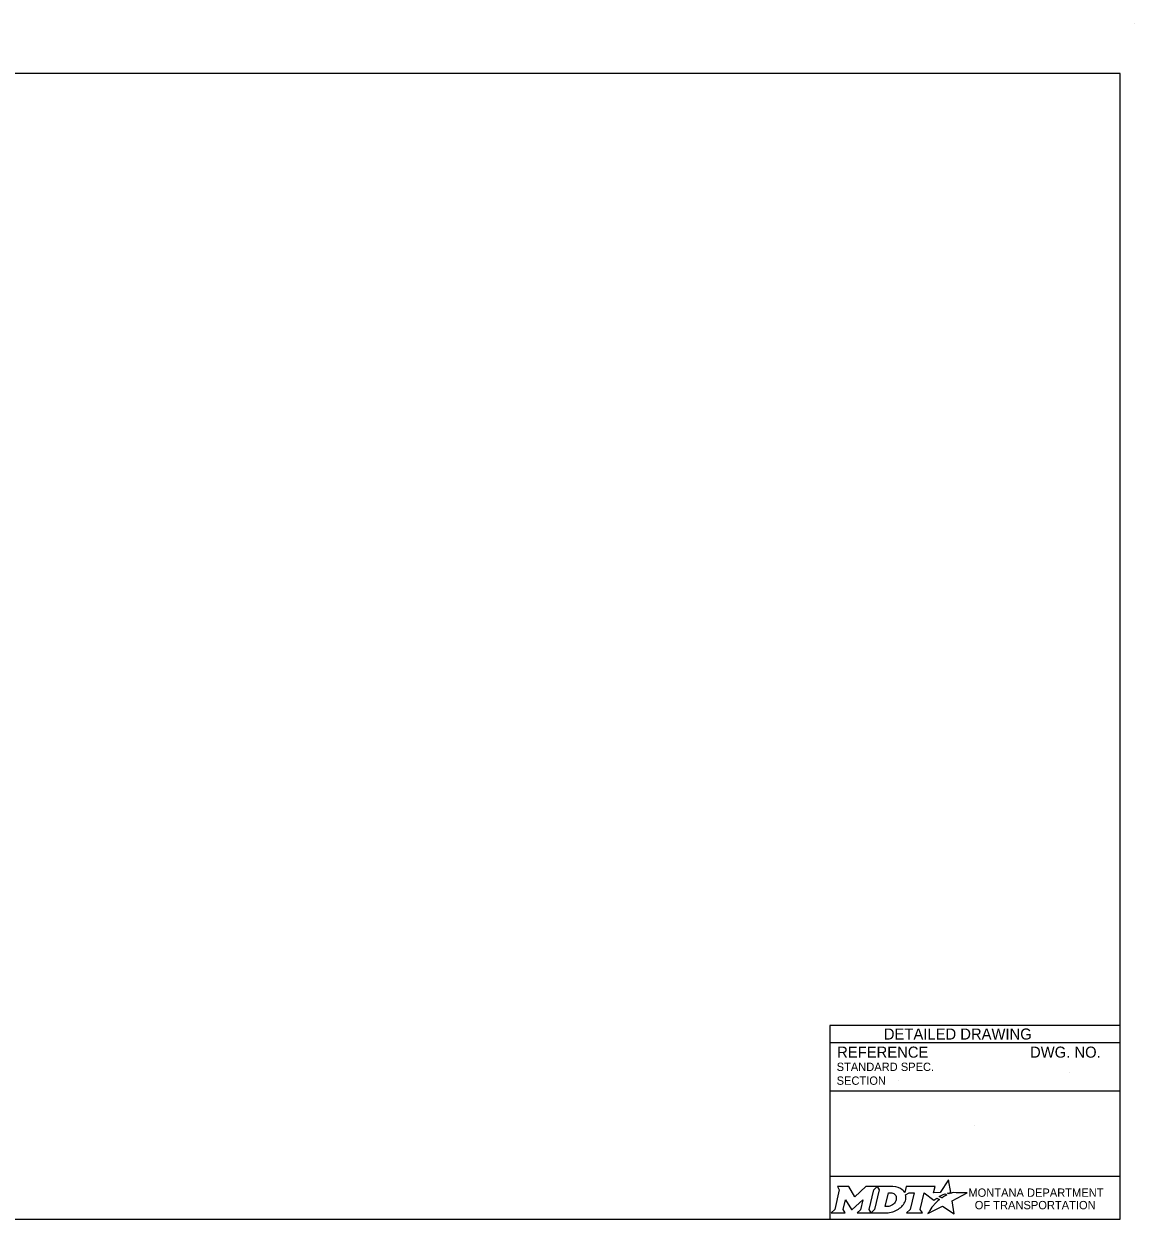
# Model space of a CAD drawing. Extents: x 49991.4 to 50021, y 49987.6 to 50011.4.
# Drawn here: x 50013.01 to 50021.04, y 49999.89 to 50008.52 of the extents above; entities that cross this region are included whole.
import ezdxf

# ---------------------------------------------------------------- set-up
doc = ezdxf.new("R2010")
doc.units = 0
for name, color, linetype in [('Default', 7, 'Continuous'), ('Level 1', 7, 'Continuous'), ('Level 4', 7, 'Continuous')]:
    doc.layers.add(name, color=color, linetype=linetype)

msp = doc.modelspace()

# ---------------------------------------------------------------- linework, layer by layer
at = {"layer": 'Default'}
for points in [[(50018.8933, 50000.1206), (50018.9074, 50000.0972), (50018.8739, 49999.9539), (50018.8482, 49999.9314), (50018.9498, 49999.9314), (50018.9363, 49999.9542), (50018.9525, 50000.0243), (50018.9962, 49999.9553), (50019.0015, 49999.9553), (50019.0766, 50000.0248), (50019.0602, 49999.9537), (50019.0355, 49999.9317), (50019.1371, 49999.9317), (50019.1233, 49999.955), (50019.1565, 50000.0974)], [(50019.1565, 50000.0974), (50019.1818, 50000.1206), (50019.0994, 50000.1206), (50019.0198, 50000.0476), (50018.9753, 50000.1203), (50018.8933, 50000.1206)], [(50019.2954, 50000.1206), (50019.1818, 50000.1206), (50019.1965, 50000.0977), (50019.1626, 49999.9539), (50019.1371, 49999.9317), (50019.2477, 49999.9317)], [(50019.7003, 50000.0679), (50019.69, 50000.0735), (50019.7016, 50000.0763), (50019.7132, 50000.0783), (50019.6958, 50000.1684), (50019.6363, 50000.0771), (50019.589, 50000.0764), (50019.5993, 50000.1205), (50019.3901, 50000.1206), (50019.38, 50000.0781), (50019.3742, 50000.0864)], [(50019.3194, 50000.0339), (50019.3182, 50000.0258), (50019.315, 50000.0165), (50019.3108, 50000.0083), (50019.3052, 50000.0008), (50019.2987, 49999.9939), (50019.2908, 49999.9876), (50019.2825, 49999.9829), (50019.2734, 49999.979), (50019.2643, 49999.9767), (50019.2551, 49999.9758), (50019.2392, 49999.9758), (50019.2628, 50000.0758), (50019.2788, 50000.0758), (50019.2864, 50000.0752), (50019.294, 50000.0733), (50019.3006, 50000.0703), (50019.3067, 50000.0661), (50019.3115, 50000.0611), (50019.3152, 50000.0551), (50019.3179, 50000.0489), (50019.3195, 50000.0415), (50019.3195, 50000.0385), (50019.3194, 50000.0339)], [(50019.3868, 50000.0615), (50019.4114, 50000.0746), (50019.4483, 50000.0746), (50019.4197, 49999.9541), (50019.3922, 49999.9314), (50019.5084, 49999.9314), (50019.4914, 49999.9543), (50019.5196, 50000.0745), (50019.5909, 50000.0228), (50019.612, 50000.0379), (50019.6317, 50000.027)], [(50019.5759, 49999.9711), (50019.5606, 49999.9467), (50019.5559, 49999.9392), (50019.5501, 49999.9306), (50019.5478, 49999.9263), (50019.6531, 49999.9794), (50019.737, 49999.9243), (50019.7239, 50000.017), (50019.8308, 50000.0754), (50019.7815, 50000.0762), (50019.7514, 50000.0766), (50019.7306, 50000.0769), (50019.7238, 50000.0754), (50019.7189, 50000.0742), (50019.7105, 50000.0719), (50019.7003, 50000.0679)], [(50019.6499, 50000.0403), (50019.6475, 50000.0386), (50019.6292, 50000.0482), (50019.6395, 50000.0539), (50019.6436, 50000.0561), (50019.6522, 50000.0601), (50019.6579, 50000.0627), (50019.6658, 50000.0657), (50019.6731, 50000.0684), (50019.6849, 50000.061), (50019.6809, 50000.0589), (50019.6763, 50000.0564), (50019.6721, 50000.0542), (50019.6671, 50000.0513), (50019.6652, 50000.0502), (50019.6625, 50000.0486), (50019.66, 50000.0472), (50019.6577, 50000.0456), (50019.6551, 50000.0438), (50019.6524, 50000.042), (50019.6499, 50000.0403)], [(50019.2934, 49999.939), (50019.3018, 49999.9416), (50019.3148, 49999.947), (50019.3352, 49999.958)], [(50019.5898, 49999.9872), (50019.5898, 49999.9872)]]:
    msp.add_lwpolyline(points, dxfattribs=at)
for centre, radius, start, end in [((50019.3185, 50000.0422), 0.0709, 339.53292, 15.85821), ((50019.2745, 50000.0595), 0.1183, 300.91025, 339.13831)]:
    msp.add_arc(centre, radius, start, end, dxfattribs=at)
for centre, major_axis, ratio, start_param, end_param in [((50019.2933, 50000.0732), (0.0834, -0.0037), 0.568097, 0.61298, 1.570796), ((50019.3489, 50000.0805), (0.0361, -0.0295), 0.469099, 1.225588, 1.570796), ((50019.6206, 50000.0173), (-0.0112, -0.0097), 0.021651, 3.157348, 6.283185), ((50019.5829, 49999.9791), (-0.00694, -0.00806), 0.008222, 0, 3.137361), ((50019.5996, 49999.9974), (-0.0098, -0.0102), 0.016458, 3.141593, 6.279097), ((50019.248, 50000.08), (0, 0.1484), 0.987302, 3.139398, 3.456847)]:
    msp.add_ellipse(centre, major_axis=major_axis, ratio=ratio, start_param=start_param, end_param=end_param, dxfattribs=at)
at = {"layer": 'Level 1'}
msp.add_line((50021.0378, 50008.5236), (50021.0378, 50008.5236), dxfattribs=at)
msp.add_lwpolyline([(50020.9378, 50008.1646), (50009.7374, 50008.1646), (50009.7374, 49999.8856), (50020.9378, 49999.8856)], close=True, dxfattribs=at)
at = {"layer": 'Level 4'}
for p, q in [((50020.9378, 50001.2856), (50018.8378, 50001.2856)), ((50018.8378, 50001.2856), (50018.8378, 49999.8856)), ((50020.9378, 50001.1606), (50018.8378, 50001.1606)), ((50020.5739, 50000.9455), (50020.5739, 50000.9455)), ((50020.9378, 50000.8106), (50018.8378, 50000.8106)), ((50019.3321, 50000.8861), (50019.3321, 50000.8861)), ((50019.8878, 50000.5615), (50019.8878, 50000.5615)), ((50020.9378, 50000.1925), (50018.8378, 50000.1925))]:
    msp.add_line(p, q, dxfattribs=at)

# ---------------------------------------------------------------- texts
at = {"layer": 'Default'}
for s, p in [('MONTANA DEPARTMENT', (50019.8403, 50000.0468)), ('OF TRANSPORTATION', (50019.8862, 49999.9568))]:
    msp.add_text(s, height=0.06, rotation=360, dxfattribs=at).set_placement(p)
at = {"layer": 'Level 4'}
for s, height, p in [('DETAILED DRAWING', 0.0799, (50019.2295, 50001.1831)), ('REFERENCE', 0.08, (50018.8914, 50001.0522)), ('DWG. NO.', 0.08, (50020.2856, 50001.0522)), ('STANDARD SPEC.', 0.06, (50018.8881, 50000.9562)), ('SECTION', 0.06, (50018.8881, 50000.8562))]:
    msp.add_text(s, height=height, dxfattribs=at).set_placement(p)

doc.saveas('drawing.dxf')
